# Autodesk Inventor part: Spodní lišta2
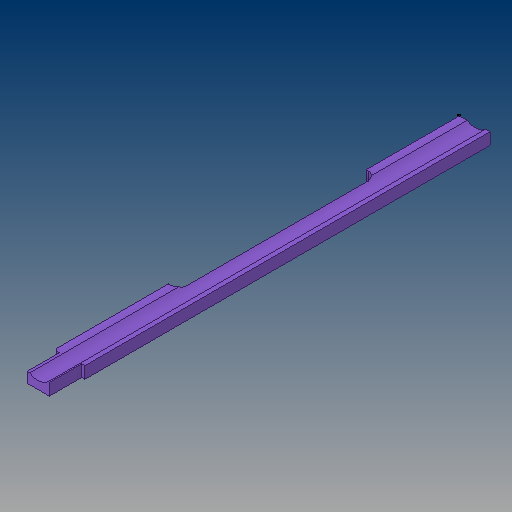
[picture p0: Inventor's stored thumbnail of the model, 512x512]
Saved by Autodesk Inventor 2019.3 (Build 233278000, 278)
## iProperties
Created: 2019-03
Part Number: Spodní lišta2
Material: Hliník 6061-AHC
Document SubType Name: Modeling
Designer: B-hon
Density: 2.7 g/cm^3
Appearance: Fialová
Author: B-hon
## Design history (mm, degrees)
sketch "Náčrt1"
  geometry: L1 (0, 0)-(48, 0); L2 (48, 0)-(48, 18.5); L3 (48, 18.5)-(0, 18.5); L4 (0, 18.5)-(0, 0)
  constraints: 8 end point, 2 parallel, 1 horizontal, 1 perpendicular
  dimensions: "d0" = 48 distance of L3.end L2.end; "d1" = 18.5 distance of L2.end L1.end
extrude "Vysunutí1" new body sketch "Náčrt1" distance "d2" = 570; taper "d3" = 0 deg
sketch "Náčrt2"
  geometry: L1 (48, 0)-(48, 18.5) reference; L2 (0, 0)-(48, 0) reference; L3 (-7.001, 16)-(12.039, 16); L4 (-7.001, 16)-(-7.001, 35); L5 (-7.001, 35)-(2, 35); A1 r 23 centre (25, 35) between (12.039, 16) and (2, 35)
  constraints: 6 end point, 2 point on circle, 1 centre point, 1 horizontal, 1 perpendicular, 1 vertical
  dimensions: "d4" = 46 diameter of A1; "d5" = 23 distance from line of L1 A1.centre (= 0.5 x d4); "d6" = 12 distance edge to line of A1 L2; "d7" = 4 distance edge to line of A1 L3
extrude "Vysunutí2" cut sketch "Náčrt2" distance "d8" = 740; taper "d9" = 0 deg
sketch "Náčrt3"
  geometry: L1 (-101.402, 424)-(12.039, 424); L2 (12.039, 424)-(12.039, 115); L3 (12.039, 115)-(-101.402, 115); L4 (-101.402, 115)-(-101.402, 424); L5 (0, 570)-(12.039, 570) reference; L6 (12.039, 0)-(0, 0) reference
  constraints: 8 end point, 2 parallel, 1 horizontal, 1 perpendicular, 1 vertical alignment
  dimensions: "d10" = 146 distance between parallel lines of L1 L5; "d19" = 115 distance between parallel lines of L6 L3
extrude "Vysunutí3" cut sketch "Náčrt3" distance "d11" = 20; taper "d12" = 0 deg
node "Upravit přímo1"
node "Upravit přímo2"
node "Pracovní rovina1"
sketch "Náčrt7"
  geometry: 1 further point
sketch "Náčrt8"
  geometry: L1 (-82.354, -455)-(15.039, -455); L2 (15.039, -455)-(15.039, -146); L3 (15.039, -146)-(-82.354, -146); L4 (-82.354, -146)-(-82.354, -455); L5 (12.039, -455)-(12.039, -146) reference; 1 further point
  constraints: 8 end point, 2 parallel, 1 horizontal, 1 perpendicular, 1 point on line
  dimensions: "d42" = 3 distance between parallel lines of L5 L2; "d49" = 0 distance from line of L3 L5.end
extrude "Vysunutí5" cut sketch "Náčrt8" extent not by distance; stored distance "d43" = 10; taper "d44" = 0 deg
fillet "Zaoblení2" dims "d45" = 12
node "Upravit přímo5"
node "Upravit přímo6"
sketch "Náčrt9"
  geometry: L1 (-9, 238.496)-(-18.486, 238.496); L2 (-18.486, 238.496)-(-18.486, 229.327); L3 (-18.486, 229.327)-(-9, 229.327); L4 (-9, 229.327)-(-9, 238.496); A1 r 12 centre (-9, 241.327) between (-12.039, 229.718) and (0, 233.39) reference; 1 further point
  constraints: 8 end point, 2 parallel, 1 horizontal, 1 perpendicular, 1 point on line, 1 tangent
extrude "Vysunutí6" cut sketch "Náčrt9" extent not by distance; stored distance "d56" = 10; taper "d57" = 0 deg
sketch "Náčrt10"
  geometry: L1 (-17.589, -3.91)-(-4.039, -3.91); L2 (-4.039, -3.91)-(-4.039, 50.6); L3 (-4.039, 50.6)-(-17.589, 50.6); L4 (-17.589, 50.6)-(-17.589, -3.91); L5 (-12.039, 0)-(-12.039, 229.327) reference; L6 (0, 0)-(-12.039, 0) reference; L7 (42.623, -3.617)-(30.961, -3.617); L8 (30.961, -3.617)-(30.961, 50.6); L9 (30.961, 50.6)-(42.623, 50.6); L10 (42.623, 50.6)-(42.623, -3.617); L11 (35.961, 685)-(35.961, 0) reference; L12 (35.961, 0)-(28.985, 0) reference; 1 further point
  constraints: 16 end point, 4 parallel, 2 horizontal, 2 perpendicular
  dimensions: "d58" = 8 distance between parallel lines of L5 L2; "d59" = 50.6 distance between parallel lines of L3 L6; "d60" = 5 distance between parallel lines of L11 L8; "d61" = 50.6 distance between parallel lines of L12 L9
extrude "Vysunutí7" cut sketch "Náčrt10" extent not by distance; stored distance "d62" = 0; taper "d63" = 0 deg
chamfer "Zkosení2" distance "d64" = 3; stored, may be unused: second distance "d65" = 2, angle "d66" = 45 deg
node "Těleso1"
feature "Posunout1" dims "d18" = -85
feature "Posunout2" dims "d22" = -7
feature "Posunout5" dims "d52" = 200
feature "Posunout6" dims "d55" = 7
other parameters: "d16" = 0, "d17" = 0, "d20" = 0, "d21" = 0, "d30" = -23, "d50" = 0, "d51" = 0, "d53" = 0, "d54" = 0
